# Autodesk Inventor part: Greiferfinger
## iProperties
Shininess: 20.0
Length Units: 11269
Angle Units: 11279
Time Units: 11290
Mass Units: 11283
Length Display Precision: 3
Angle Display Precision: 2
Company: Rhodius GmbH
Part Number: Greiferfinger
Material: Standard
Document SubType Name: Modeling
Cost Center: Abtlg. Technik
Designer: KOPP
Created: 2003-05
Description: Greiferfinger
Density: 0.0
Volumn: 0.0
Area: 0.0
PropertySet Name: Model Information
Control State: 0
Master: False
Checked Out: False
Author: KOPP
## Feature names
1. Extrusion1
2. Bohrung1 [Hole]
3. Bohrung2 [Hole]
